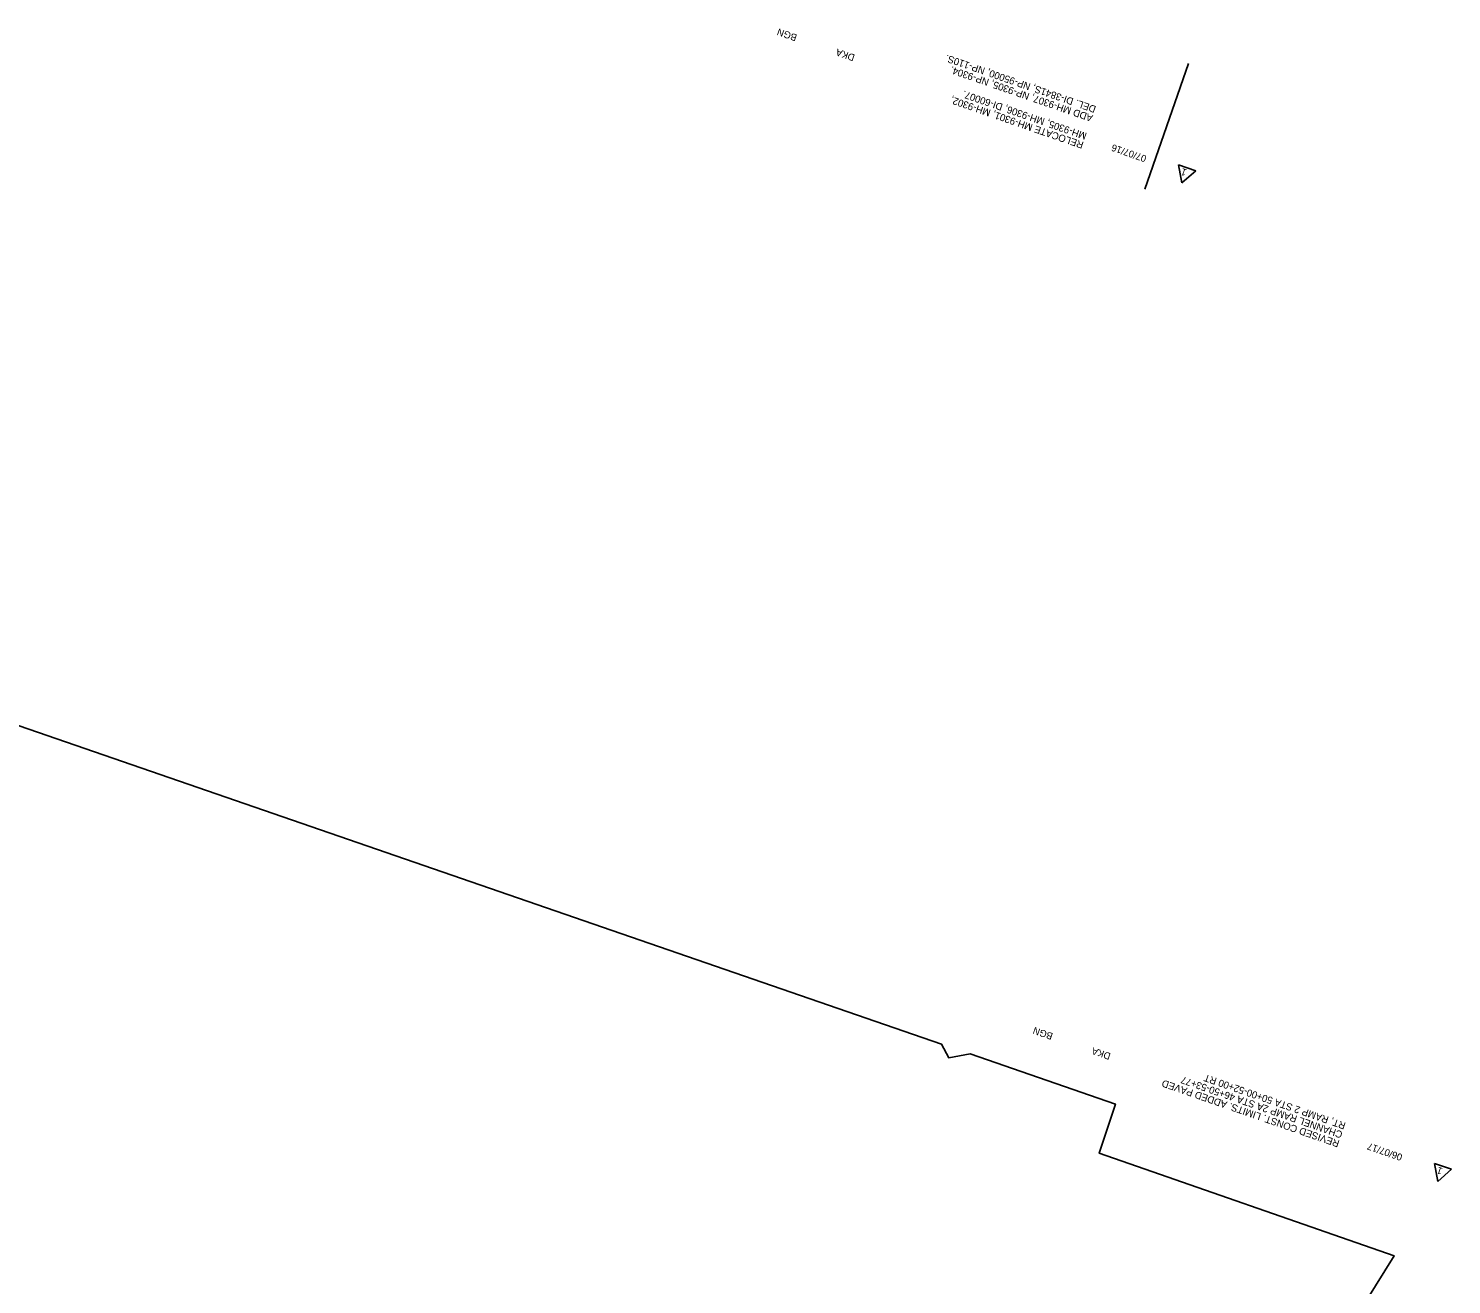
# Model space of a CAD drawing. Extents: x 1607775 to 1609652, y 1093977 to 1095566.
# Drawn here: x 1608751 to 1609652, y 1094771 to 1095566 of the extents above; entities that cross this region are included whole.
import ezdxf

# ---------------------------------------------------------------- set-up
doc = ezdxf.new("R2010")
doc.units = 0
doc.layers.add('RD_PD_DR_ErosCtrl', color=7, linetype='Continuous')
doc.layers.add('RD_Sketch1', color=7, linetype='Continuous')

msp = doc.modelspace()

# ---------------------------------------------------------------- linework, layer by layer
at = {"layer": 'RD_PD_DR_ErosCtrl'}
msp.add_lwpolyline([(1609319.26, 1094082.92), (1609257.16, 1093976.84), (1607774.66, 1094490.39), (1607913.49, 1094758.18), (1608083.85, 1095087.22), (1608184.77, 1095282.94), (1608412.15, 1095241.23), (1608411.67, 1095239.7), (1609329.12, 1094923.25), (1609333.64, 1094914.63), (1609347.07, 1094917.06), (1609439, 1094885.35), (1609428.8, 1094854.27), (1609615.32, 1094789.49), (1609546.66, 1094678.85), (1609459.72, 1094656.09), (1609449.74, 1094513.93), (1609414.43, 1094518.3), (1609397.89, 1094407.56), (1609403.67, 1094397.48), (1609379.74, 1094297.75), (1609387.82, 1094283.49), (1609353.45, 1094193.74), (1609389.72, 1094179.44)], close=True, dxfattribs=at)
msp.add_lwpolyline([(1609319.26, 1094082.92), (1609257.16, 1093976.84), (1607774.66, 1094490.39), (1607913.49, 1094758.18), (1608083.85, 1095087.22), (1608184.77, 1095282.94), (1608412.15, 1095241.23), (1608411.67, 1095239.7), (1609329.12, 1094923.25), (1609333.64, 1094914.63), (1609347.07, 1094917.06), (1609439, 1094885.35), (1609428.8, 1094854.27), (1609615.32, 1094789.49), (1609546.66, 1094678.85), (1609459.72, 1094656.09), (1609449.74, 1094513.93), (1609414.43, 1094518.3), (1609397.89, 1094407.56), (1609403.67, 1094397.48), (1609379.74, 1094297.75), (1609387.82, 1094283.49), (1609353.45, 1094193.74), (1609389.72, 1094179.44)], close=True, dxfattribs=at)
msp.add_lwpolyline([(1609319.26, 1094082.92), (1609257.16, 1093976.84), (1607774.66, 1094490.39), (1607913.49, 1094758.18), (1608083.85, 1095087.22), (1608184.77, 1095282.94), (1608412.15, 1095241.23), (1608411.67, 1095239.7), (1609329.12, 1094923.25), (1609333.64, 1094914.63), (1609347.07, 1094917.06), (1609439, 1094885.35), (1609428.8, 1094854.27), (1609615.32, 1094789.49), (1609546.66, 1094678.85), (1609459.72, 1094656.09), (1609449.74, 1094513.93), (1609414.43, 1094518.3), (1609397.89, 1094407.56), (1609403.67, 1094397.48), (1609379.74, 1094297.75), (1609387.82, 1094283.49), (1609353.45, 1094193.74), (1609389.72, 1094179.44)], close=True, dxfattribs=at)
msp.add_lwpolyline([(1609319.26, 1094082.92), (1609257.16, 1093976.84), (1607774.66, 1094490.39), (1607913.49, 1094758.18), (1608083.85, 1095087.22), (1608184.77, 1095282.94), (1608412.15, 1095241.23), (1608411.67, 1095239.7), (1609329.12, 1094923.25), (1609333.64, 1094914.63), (1609347.07, 1094917.06), (1609439, 1094885.35), (1609428.8, 1094854.27), (1609615.32, 1094789.49), (1609546.66, 1094678.85), (1609459.72, 1094656.09), (1609449.74, 1094513.93), (1609414.43, 1094518.3), (1609397.89, 1094407.56), (1609403.67, 1094397.48), (1609379.74, 1094297.75), (1609387.82, 1094283.49), (1609353.45, 1094193.74), (1609389.72, 1094179.44)], close=True, dxfattribs=at)
msp.add_lwpolyline([(1609319.26, 1094082.92), (1609257.16, 1093976.84), (1607774.66, 1094490.39), (1607913.49, 1094758.18), (1608083.85, 1095087.22), (1608184.77, 1095282.94), (1608412.15, 1095241.23), (1608411.67, 1095239.7), (1609329.12, 1094923.25), (1609333.64, 1094914.63), (1609347.07, 1094917.06), (1609439, 1094885.35), (1609428.8, 1094854.27), (1609615.32, 1094789.49), (1609546.66, 1094678.85), (1609459.72, 1094656.09), (1609449.74, 1094513.93), (1609414.43, 1094518.3), (1609397.89, 1094407.56), (1609403.67, 1094397.48), (1609379.74, 1094297.75), (1609387.82, 1094283.49), (1609353.45, 1094193.74), (1609389.72, 1094179.44)], close=True, dxfattribs=at)
msp.add_lwpolyline([(1609319.26, 1094082.92), (1609257.16, 1093976.84), (1607774.66, 1094490.39), (1607913.49, 1094758.18), (1608083.85, 1095087.22), (1608184.77, 1095282.94), (1608412.15, 1095241.23), (1608411.67, 1095239.7), (1609329.12, 1094923.25), (1609333.64, 1094914.63), (1609347.07, 1094917.06), (1609439, 1094885.35), (1609428.8, 1094854.27), (1609615.32, 1094789.49), (1609546.66, 1094678.85), (1609459.72, 1094656.09), (1609449.74, 1094513.93), (1609414.43, 1094518.3), (1609397.89, 1094407.56), (1609403.67, 1094397.48), (1609379.74, 1094297.75), (1609387.82, 1094283.49), (1609353.45, 1094193.74), (1609389.72, 1094179.44)], close=True, dxfattribs=at)
at = {"layer": 'RD_Sketch1'}
for p, q in [((1609485.3, 1095543.53), (1609457.76, 1095464.01)), ((1609479.06, 1095479.43), (1609481.12, 1095467.98)), ((1609489.82, 1095475.71), (1609479.06, 1095479.43)), ((1609481.12, 1095467.98), (1609489.82, 1095475.71)), ((1609640.92, 1094847.85), (1609642.98, 1094836.4)), ((1609651.68, 1094844.12), (1609640.92, 1094847.85)), ((1609642.98, 1094836.4), (1609651.68, 1094844.12))]:
    msp.add_line(p, q, dxfattribs=at)

# ---------------------------------------------------------------- texts
for s, height, p in [('BGN', 4.4, (1609238.02, 1095561.63)), ('DKA', 4.4, (1609274.58, 1095548.98)), ('DEL. DI-3841S, NP-95000, NP-110S.', 4.5, (1609427.17, 1095516.38)), ('ADD MH-9307, NP-9305, NP-9304.', 4.5, (1609425.21, 1095510.72)), ('MH-9305, MH-9306, DI-60007.', 4.5, (1609421.29, 1095499.4)), ('RELOCATE MH-9301, MH-9302, ', 4.5, (1609419.33, 1095493.75)), ('07/07/16', 4.4, (1609459.11, 1095485.09)), ('1', 4.4, (1609484.55, 1095476.28)), ('BGN', 4.4, (1609399.89, 1094930.05)), ('DKA', 4.4, (1609436.44, 1094917.39)), ('RT, RAMP 2 STA 50+00-52+00 RT', 4.5, (1609585.11, 1094873.48)), ('REVISED CONST. LIMITS. ADDED PAVED', 4.5, (1609581.19, 1094862.16)), ('CHANNEL RAMP 2A STA 46+50-53+77', 4.5, (1609583.15, 1094867.82)), ('06/07/17', 4.4, (1609620.98, 1094853.5)), ('1', 4.4, (1609646.42, 1094844.7))]:
    msp.add_text(s, height=height, rotation=160.90294, dxfattribs=at).set_placement(p)

doc.saveas('drawing.dxf')
